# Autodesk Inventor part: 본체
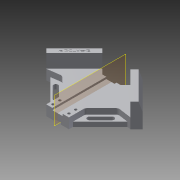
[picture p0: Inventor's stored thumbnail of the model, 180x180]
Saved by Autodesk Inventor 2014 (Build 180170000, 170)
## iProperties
Created: 2020-05
Part Number: 본체
Material: Aluminum 6061
Document SubType Name: Modeling
Designer: kh
Density: 2.71 g/cm^3
Appearance: Aluminum - Flat
Mass: 571.887 g
Surface Area: 407.089 cm^2
Volume: 211.028 cm^3
Author: kh
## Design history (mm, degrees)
sketch "Sketch1"
  geometry: L1 (84.853, 0)-(0, -84.853); L2 (0, -84.853)-(-84.853, 0); L3 (-84.853, 0)-(0, 84.853); L4 (0, 84.853)-(84.853, 0); L5 (84.853, 0)-(-84.853, 0); L6 (0, -84.853)-(0, 84.853); 3 further points
  constraints: 12 end point, 3 midpoint, 2 parallel, 2 perpendicular, 1 coincident, 1 horizontal
  dimensions: "d1" = 120 distance of L2.end L3.end
extrude "Extrusion1" new body sketch "Sketch1" distance "d2" = 42; taper "d3" = 0 deg
sketch "Sketch2"
  geometry: L1 (0, -84.853)-(84.853, 0) reference; L2 (84.853, 0)-(0, 84.853) reference; L3 (0, 84.853)-(-84.853, 0) reference; L4 (-84.853, 0)-(0, -84.853) reference; L5 (-84.853, 0)-(-74.246, -10.607); L6 (-74.246, -10.607)-(0, 63.64); L7 (10.607, 74.246)-(0, 84.853); L8 (0, 84.853)-(-84.853, 0); L9 (84.853, 0)-(74.246, -10.607); L10 (74.246, -10.607)-(0, 63.64); L11 (-10.607, 74.246)-(0, 84.853); L12 (0, 84.853)-(84.853, 0); L13 (-74.246, -10.607)-(0, -84.853); L14 (0, -84.853)-(74.246, -10.607); 1 further point
  constraints: 20 end point, 4 parallel, 4 perpendicular, 2 point on line
  dimensions: "d4" = 15 distance between parallel lines of L12 L10; "d5" = 15 distance between parallel lines of L3 L6
extrude "Extrusion2" cut sketch "Sketch2" distance "d6" = 24; taper "d7" = 0 deg
sketch "Sketch4"
  geometry: L1 (84.853, 0)-(0, -84.853) reference; L2 (0, -84.853)-(-84.853, 0) reference; L3 (-84.853, 0)-(0, 84.853) reference; L4 (0, 84.853)-(84.853, 0) reference; L5 (-20, -64.853)-(20, -64.853); L6 (-20, -64.853)-(0, -84.853); L7 (0, -84.853)-(20, -64.853); 1 further point
  constraints: 6 end point, 2 point on line, 1 collinear, 1 horizontal, 1 parallel
  dimensions: "d9" = 40 distance of L5.start L5.end
extrude "Extrusion3" cut sketch "Sketch4" stored distance "d10" = 24; taper "d11" = 0 deg
sketch "Sketch5"
  geometry: L1 (20, -64.853)-(-20, -64.853) reference; L2 (-20, -64.853)-(-84.853, 0) reference; L3 (-84.853, 0)-(0, 84.853) reference; L4 (0, 84.853)-(84.853, 0) reference; L5 (84.853, 0)-(20, -64.853) reference; L6 (-74.246, -10.607)-(0, 63.64) reference; L7 (-20, -36.569)-(-49.497, -7.071); L8 (-49.497, -7.071)-(-74.246, -10.607); L9 (-20, -36.569)-(-20, -64.853); L10 (0, 0)-(0, -17.922); L11 (-73.934, -10.919)-(-20, -64.853); L12 (-74.246, -10.607)-(-73.934, -10.919)
  constraints: 12 end point, 2 collinear, 2 perpendicular, 1 parallel, 1 point on line
  dimensions: "d15" = 30 distance from line of L3 L7.end; "d16" = 20 distance between parallel lines of L2 L7
extrude "Extrusion4" cut sketch "Sketch5" distance "d17" = 18; taper "d18" = 0 deg
workplane "Work Plane1"
sketch "Sketch6"
  geometry: L1 (-49.497, -7.071)-(-74.246, -10.607) reference; L2 (-74.246, -10.607)-(-84.853, 0) reference; L3 (-84.853, 0)-(0, 84.853) reference; L4 (0, 84.853)-(84.853, 0) reference; L5 (84.853, 0)-(20, -64.853) reference; L6 (20, -64.853)-(-20, -64.853) reference; L7 (-20, -64.853)-(-20, -36.569) reference; L8 (-20, -36.569)-(-49.497, -7.071) reference; L9 (-68.059, -9.723)-(-20, -57.782); L10 (-20, -36.569)-(-20, -57.782); L11 (-20, -36.569)-(-49.497, -7.071); L12 (-68.059, -9.723)-(-49.497, -7.071); 1 further point
  constraints: 8 end point, 2 collinear, 2 parallel, 2 point on line
  dimensions: "d20" = 5 distance between parallel lines of L9 L2
extrude "Extrusion5" join sketch "Sketch6" distance "d21" = 8; taper "d22" = 0 deg
sketch "Sketch7"
  geometry: L1 (-68.059, -9.723)-(-74.246, -10.607) reference; L2 (-74.246, -10.607)-(-84.853, 0) reference; L3 (-84.853, 0)-(0, 84.853) reference; L4 (0, 84.853)-(84.853, 0) reference; L5 (84.853, 0)-(20, -64.853) reference; L6 (20, -64.853)-(-20, -64.853) reference; L7 (-20, -64.853)-(-20, -57.782) reference; L8 (-20, -57.782)-(-68.059, -9.723) reference; L9 (-74.246, -10.607)-(-49.497, -7.071) reference; L10 (-49.497, -7.071)-(-20, -36.569) reference; L11 (-68.059, -9.723)-(-49.497, -7.071) reference; L12 (-20, -57.782)-(-68.059, -9.723) reference; L13 (-20, -36.569)-(-20, -57.782) reference; L14 (-49.497, -18.385)-(-29.698, -38.184); L15 (-46.669, -15.556)-(-26.87, -35.355); L16 (-32.527, -41.012)-(-52.326, -21.213); L17 (-26.87, -35.355)-(-32.527, -41.012); L18 (-46.669, -15.556)-(-52.326, -21.213); A1 r 4 centre (-49.497, -18.385) between (-46.669, -15.556) and (-52.326, -21.213); A2 r 4 centre (-29.698, -38.184) between (-32.527, -41.012) and (-26.87, -35.355); 2 further points
  constraints: 12 end point, 4 point on circle, 4 tangent, 2 centre point, 2 parallel, 2 perpendicular, 1 midpoint
  dimensions: "d27" = 8 distance between parallel lines of L15 L16; "d29" = 12 distance from line of point (-39.598, -28.284) L2; "d30" = 38 distance from line of L15.start L3; "d32" = 36 dimension on A2 A1
extrude "Extrusion6" cut sketch "Sketch7" stored distance "d33" = 8; taper "d34" = 0 deg
mirror "Mirror1"
mirror "Mirror2"
sketch "Sketch8"
  geometry: L1 (84.853, 0)-(0, 84.853) reference; L2 (0, 84.853)-(35.355, 49.497); L3 (0, 84.853)-(-84.853, 0) reference; L4 (0, 84.853)-(-35.355, 49.497); L5 (-35.355, 49.497)-(-16.005, 30.147); L6 (16.005, 30.147)-(35.355, 49.497); L7 (0, 0)-(0, 13.949); L8 (0, 0)-(12.313, 0); L9 (16.005, 30.147)-(-16.005, 30.147); L10 (-20, -64.853)-(20, -64.853) reference
  constraints: 14 end point, 2 parallel, 2 perpendicular, 1 collinear, 1 point on line, 1 vertical
  dimensions: "d35" = 50 distance of L1.end L2.end; "d36" = 50 distance of L1.end L4.end; "d37" = 95 distance between parallel lines of L10 L9
extrude "Extrusion7" cut sketch "Sketch8" stored distance "d38" = 8; taper "d39" = 0 deg
chamfer "Chamfer1" distance "d40" = 5; stored, may be unused: second distance "d41" = 15, angle "d42" = 45 deg
chamfer "Chamfer2" distance "d43" = 5; stored, may be unused: second distance "d44" = 15, angle "d45" = 45 deg
sketch "Sketch9"
  geometry: L1 (40, 0)-(0, 0) reference; L2 (40, 18)-(40, 0) reference; L3 (0, 18)-(40, 18) reference; L4 (0, 0)-(0, 18) reference; L5 (11, 18)-(29, 18); L6 (29, 18)-(29, 14.5); L7 (29, 14.5)-(11, 14.5); L8 (11, 14.5)-(11, 18); L9 (20, 0)-(20, 5.412); L10 (14, 0)-(26, 0); L11 (26, 0)-(26, 3); L12 (26, 3)-(14, 3); L13 (14, 3)-(14, 0)
  constraints: 18 end point, 5 parallel, 4 point on line, 2 perpendicular, 2 other
  dimensions: "d46" = 12 distance between parallel lines of L11 L13; "d47" = 18 distance between parallel lines of L6 L8; "d48" = 3.5 distance between parallel lines of L7 L3; "d49" = 3 distance between parallel lines of L1 L12
extrude "Extrusion8" cut sketch "Sketch9" stored distance "d50" = 8; taper "d51" = 0 deg
sketch "Sketch10"
  geometry: L1 (-9, -64.853)-(-9, 30.147) reference; L2 (-9, 30.147)-(-16.005, 30.147) reference; L3 (-16.005, 30.147)-(-24.749, 38.891) reference; L4 (-74.246, -10.607)-(-24.749, 38.891) reference; L5 (-74.246, -10.607)-(-49.497, -7.071) reference; L6 (-49.497, -7.071)-(-20, -36.569) reference; L7 (-20, -36.569)-(-20, -64.853) reference; L8 (-20, -64.853)-(-9, -64.853) reference; L9 (9, 30.147)-(9, -64.853) reference; L10 (9, -64.853)-(20, -64.853) reference; L11 (20, -64.853)-(20, -36.569) reference; L12 (20, -36.569)-(49.497, -7.071) reference; L13 (49.497, -7.071)-(74.246, -10.607) reference; L14 (24.749, 38.891)-(74.246, -10.607) reference; L15 (24.749, 38.891)-(16.005, 30.147) reference; L16 (16.005, 30.147)-(9, 30.147) reference; L17 (0, 0)-(0, -8.534); 4 further points
  constraints: 2 end point, 1 perpendicular, 1 symmetric about line
  dimensions: "d52" = 28 distance of point (14, -58.853) point (-14, -58.853); "d53" = 6 distance from line of L10 point (14, -58.853); "d54" = 12 distance of point (14, -58.853) point (14, -46.853); "d55" = 12 distance of point (-14, -58.853) point (-14, -46.853)
hole "Hole1" sketch "Sketch10" at (-14, -58.853), (-14, -46.853), (14, -46.853), (14, -58.853) diameter "d56" = 4.5; stored, may be unused: countersink angle "d60" = 90 deg, drill point angle "d62" = 0 deg; dims "d57" = 6, "d58" = 4, "d59" = 2, "d61" = 8
sketch "Sketch11"
  geometry: C1 r 2.25 at (-14, -58.853) reference; C2 r 2.25 at (-14, -46.853) reference; C3 r 2.25 at (14, -46.853) reference; C4 r 2.25 at (14, -58.853) reference; 5 further points
  constraints: 4 coincident
hole "Hole2" sketch "Sketch11" at (-14, -46.853), (-14, -58.853), (14, -58.853), (14, -46.853) diameter "d63" = 8; stored, may be unused: countersink angle "d67" = 90 deg, drill point angle "d69" = 0 deg; dims "d64" = 6, "d65" = 4, "d66" = 2, "d68" = 10
fillet "Fillet1" dims "d70" = 5
sketch "Sketch12"
  geometry: L1 (-45.365, 29.325)-(-64.681, 10.01); L2 (-64.681, 10.01)-(-60.701, 6.03); L3 (-60.701, 6.03)-(-41.385, 25.346); L4 (-41.385, 25.346)-(-45.365, 29.325); L5 (-81.317, -3.536)-(-31.82, 45.962) reference; L6 (-81.317, -3.536)-(-74.246, -10.607) reference; L7 (-74.246, -10.607)-(-24.749, 38.891) reference; L8 (-24.749, 38.891)-(-31.82, 45.962) reference; L9 (-28.284, 42.426)-(-53.033, 17.678); 3 further points
  constraints: 2 end point, 1 coincident, 1 midpoint, 1 parallel, 2 other
  dimensions: "d71" = 35 distance of L9.end L9.start
emboss "Emboss1" sketch "Sketch12" dims "d6" = 24, "d72" = 0.5, "d73" = 0
workplane "Work Plane2"
body "Solid1"
node "Projected Loop1"
node "Projected Loop3"
node "Projected Loop4"
node "Projected Loop5"
node "Projected Loop6"
node "Projected Loop7"
node "Projected Loop8"
node "Projected Loop9"
node "Projected Loop10"
node "Projected Loop11"
